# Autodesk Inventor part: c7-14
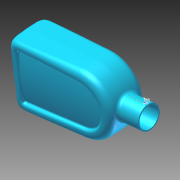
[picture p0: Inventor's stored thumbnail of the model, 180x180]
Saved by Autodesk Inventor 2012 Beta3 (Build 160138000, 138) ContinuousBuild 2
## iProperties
Created: 2010-12
Part Number: c7-14
Material: Default
Document SubType Name: Modeling
Designer: Beta-8540w
Density: 1 g/cm^3
Author: Beta-8540w
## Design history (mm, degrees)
sketch "Sketch1"
  geometry: L1 (-25, 0)-(25, 0); L2 (25, 0)-(25, 80); L3 (25, 80)-(-25, 80); L4 (-25, 80)-(-25, 0); 2 further points
  constraints: 8 end point, 2 parallel, 1 coincident, 1 horizontal, 1 midpoint, 1 perpendicular
  dimensions: "d0" = 50 distance of L3.end L2.end; "d1" = 80 distance of L2.end L1.end
extrude "Extrusion1" new body sketch "Sketch1" distance "d2" = 15; taper "d3" = 0 deg
feature "FaceDraft1" dims angle "d4" = -2 deg
fillet "Fillet1"
fillet "Fillet2" dims "d5" = 8, "d6" = 8, "d7" = 8, "d8" = 8, "d9" = 8, "d10" = 8, "d11" = 3, "d12" = 3, "d13" = 3, "d14" = 6, "d15" = 5
sketch "Sketch2"
  geometry: L1 (5.522, 12)-(38.474, 12) reference; L2 (0, 0)-(43.996, 0) reference; L3 (41.757, 6.83)-(41.995, 0); L4 (41.925, 2)-(2.071, 2); L5 (2.001, 0)-(2.24, 6.83); L6 (5.522, 10)-(38.474, 10); A1 r 5.284 centre (38.474, 6.716) between (43.755, 6.9) and (38.474, 12) reference; A2 r 5.284 centre (5.522, 6.716) between (5.522, 12) and (0.241, 6.9) reference; A3 r 3.284 centre (38.474, 6.716) between (41.757, 6.83) and (38.474, 10); A4 r 3.284 centre (5.522, 6.716) between (5.522, 10) and (2.24, 6.83); 1 further point
  constraints: 8 end point, 4 point on circle, 4 point on line, 2 centre point, 1 other
  dimensions: "d16" = 2 radial gap between concentric circles of A2 A4
extrude "Extrusion2" cut sketch "Sketch2" distance "d17" = 1; taper "d18" = 0 deg
feature "FaceDraft2" dims angle "d19" = 15 deg
sketch "Sketch3" dims "d20" = 2.5
  geometry: L1 (16.476, 3)-(-16.476, 3) reference; L2 (16.476, 5.5)-(-16.476, 5.5); 9 further points
  constraints: 2 end point, 2 parallel, 1 horizontal alignment, 19 other
extrude "Extrusion3" cut sketch "Sketch3" distance "d21" = 3; taper "d22" = 0 deg
feature "FaceDraft3" dims angle "d23" = 10 deg
workplane "Work Plane1"
sketch "Sketch4"
  geometry: L1 (41.1, -1.222)-(41.476, -12) reference; L2 (41.476, -12)-(-8.524, -12) reference; L3 (-8.524, -12)-(-8.147, -1.222) reference; L4 (-3.776, 3)-(-1.272, 3) reference; L5 (-0.743, 0)-(33.695, 0) reference; L6 (34.225, 3)-(36.728, 3) reference; L7 (-11.024, -1.856)-(43.976, -1.856); A1 r 100 centre (16.476, -98) between (43.976, -1.856) and (-11.024, -1.856); 2 further points
  constraints: 2 end point, 2 point on circle, 1 centre point, 1 midpoint, 1 parallel, 1 vertical alignment, 4 other
  dimensions: "d25" = 100 radius of A1; "d26" = 14 distance edge to line of A1 L2; "d27" = 55 distance of L7.start L7.end
extrude_surface "ExtrusionSrf1" sketch "Sketch4" dims "d28" = 86, "d29" = 0
feature "Replace Face1"
fillet "Fillet3" dims "d34" = 1, "d35" = 2
mirror "Mirror1"
fillet "Fillet4" dims "d36" = 20
workplane "Work Plane3"
sketch "Sketch6"
  geometry: C1 r 9 at (0, 0); 1 further point
  constraints: 1 centre point, 1 coincident
  dimensions: "d38" = 18 diameter of C1
extrude "Top Boss" join sketch "Sketch6" distance "d39" = 16; taper "d40" = 0 deg
fillet "Fillet5" dims "d41" = 3
shell "Shell1" dims "d44" = 1
sketch "Sketch7"
  geometry: L1 (-9, 80.285)-(-9, 96) reference; C1 r 0.75 at (-9, 94); 1 further point
  constraints: 1 centre point, 1 point on line
  dimensions: "d42" = 2 distance of L1.end C1.centre; "d43" = 1.5 diameter of C1
body "Solid1"
body "Srf1"
node "Project Cut Edges1"
